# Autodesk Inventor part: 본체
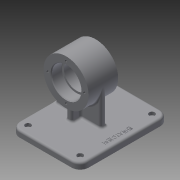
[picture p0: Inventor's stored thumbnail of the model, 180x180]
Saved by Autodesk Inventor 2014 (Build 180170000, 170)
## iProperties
Created: 2019-09
Part Number: 본체
Material: Generic
Document SubType Name: Modeling
Designer: kh
Density: 1 g/cm^3
Appearance: Default
Author: kh
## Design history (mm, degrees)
sketch "스케치1"
  geometry: C1 r 32 at (0, 0); 1 further point
  constraints: 1 centre point, 1 coincident
  dimensions: "d0" = 64 diameter of C1
extrude "돌출1" new body sketch "스케치1" distance "d1" = 42; taper "d2" = 0 deg
node "작업 평면1"
sketch "스케치2"
  geometry: L1 (-62, 84)-(36, 84); L2 (36, 84)-(36, -42); L3 (36, -42)-(-62, -42); L4 (-62, -42)-(-62, 84); L5 (32, 42)-(-32, 42) reference; L6 (-32, 0)-(-32, 42) reference; 3 further points
  constraints: 8 end point, 2 midpoint, 2 parallel, 1 horizontal, 1 perpendicular
  dimensions: "d4" = 98 distance of L1.start L1.end; "d5" = 126 distance of L1.end L2.end; "d6" = 62 distance from line of point (0, 42) L4; "d7" = 63 distance from line of L1 point (-32, 21)
extrude "돌출2" join sketch "스케치2" distance "d8" = 9; taper "d9" = 0 deg
sketch "스케치3"
  geometry: C1 r 21 at (0, 0); 1 further point
  constraints: 1 centre point, 1 coincident
  dimensions: "d10" = 42 diameter of C1
extrude "돌출3" cut sketch "스케치3" distance "d11" = 15; taper "d12" = 0 deg
sketch "스케치4"
  geometry: 1 further point
hole "구멍1" sketch "스케치4" at (0, 0) diameter "d13" = 36; stored, may be unused: countersink angle "d17" = 82 deg, drill point angle "d19" = 0 deg; dims "d14" = 19.05, "d15" = 42, "d16" = 15, "d18" = 12
node "작업 평면2"
sketch "스케치5"
  geometry: L1 (-32, 0)-(-32, 42) reference; L2 (-50, -42)-(-50, 84) reference; L3 (-26.204, 38)-(-50, 38); L4 (-26.204, 4)-(-50, 4); L5 (-26.204, 38)-(-26.204, 4); 2 further points
  constraints: 6 end point, 3 perpendicular, 2 point on line, 1 midpoint
  dimensions: "d21" = 17 distance from line of point (-32, 21) L3; "d22" = 17 distance from line of point (-32, 21) L4; "d23" = 23.79616 distance between parallel lines of L2 L5
extrude "돌출4" join sketch "스케치5" distance "d24" = 4; taper "d26" = 0 deg; dims "d25" = 4, "d27" = 0
node "작업 평면3"
sketch "스케치6"
  geometry: L1 (62, -50)-(-36, -50) reference; L2 (-32, 0)-(-32, -50); L3 (32, 0)-(32, -50); L4 (-29.773, -50)-(32, -50); A1 r 32 centre (0, 0) between (-32, 0) and (32, 0) reference; A2 r 32 centre (0, 0) between (-32, 0) and (32, 0); 1 further point
  constraints: 6 end point, 4 point on circle, 4 tangent, 3 point on line, 2 perpendicular, 1 centre point, 1 collinear
extrude "돌출5" join sketch "스케치6" distance "d29" = 4; taper "d31" = 0 deg; dims "d30" = 4, "d32" = 0
sketch "스케치7"
  geometry: A1 r 26 centre (0, 0) between (0, 26) and (26, 0); 3 further points
  constraints: 4 point on circle, 2 horizontal alignment, 2 vertical alignment, 1 centre point, 1 coincident
  dimensions: "d33" = 52 diameter of A1
hole "구멍2" sketch "스케치7" at (0, 26), (26, 0), (0, -26), (-26, 0) diameter "d34" = 3.2512; stored, may be unused: countersink angle "d38" = 82 deg, drill point angle "d40" = 118 deg; dims "d35" = 8, "d36" = 9.525, "d37" = 6.35, "d39" = 10
sketch "스케치8"
  geometry: C1 r 1.626 at (0, 26) reference; C2 r 1.626 at (26, 0) reference; C3 r 1.626 at (0, -26) reference; C4 r 1.626 at (-26, 0) reference; 1 further point
hole "구멍3" sketch "스케치8" at (0, 26), (-26, 0), (0, -26), (26, 0) diameter "d41" = 3.2512; stored, may be unused: countersink angle "d45" = 82 deg, drill point angle "d47" = 118 deg; dims "d42" = 8, "d43" = 9.525, "d44" = 6.35, "d46" = 10
fillet "모깎기1" dims "d48" = 3
fillet "모깎기2" dims "d49" = 3
fillet "모깎기3" dims "d50" = 12
sketch "스케치9"
  geometry: L1 (62, -72)-(62, 30) reference; L2 (-36, 30)-(-36, -72) reference; L3 (-24, -84)-(50, -84) reference; L4 (50, 42)-(-24, 42) reference; 5 further points
  constraints: 2 horizontal alignment
  dimensions: "d51" = 12 distance from line of L1 point (50, 30); "d52" = 12 distance from line of point (-24, 30) L2; "d53" = 12 distance from line of L1 point (50, -72); "d54" = 12 distance from line of point (-24, -72) L2; "d56" = 12 distance from line of point (-24, -72) L3; "d57" = 12 distance from line of point (-24, 30) L4
hole "구멍4" sketch "스케치9" at (50, 30), (-24, 30), (50, -72), (-24, -72) diameter "d58" = 4.5; stored, may be unused: countersink angle "d62" = 82 deg, drill point angle "d64" = 0 deg; dims "d59" = 8, "d60" = 8, "d61" = 4.4, "d63" = 10
chamfer "모따기1" distance "d65" = 1; stored, may be unused: second distance "d66" = 3.175, angle "d67" = 45 deg
fillet "모깎기4" dims "d68" = 3
fillet "모깎기5" dims "d69" = 0.3
sketch "스케치10"
  geometry: L1 (55.004, -0.245)-(55.004, -41.755); L2 (55.004, -41.755)-(48.996, -41.755); L3 (48.996, -41.755)-(48.996, -0.245); L4 (48.996, -0.245)-(55.004, -0.245); L5 (-36, -26.472)-(-36, -72) reference; L6 (-24, -84)-(50, -84) reference; L7 (62, -72)-(62, 30) reference; 3 further points
  constraints: 2 midpoint, 1 parallel, 2 other
  dimensions: "d70" = 63 distance from line of point (55.004, -21) L6; "d71" = 10 distance from line of L7 point (52, -41.755); "d72" = 6.00863 distance between parallel lines of L1 L3; "d73" = 41.51049 distance from line of L4 point (52, -41.755)
extrude "돌출6" join sketch "스케치10" distance "d74" = 0.5; taper "d75" = 0 deg
node "솔리드1"
other parameters: "d3" = -59, "d20" = 0, "d28" = 21
